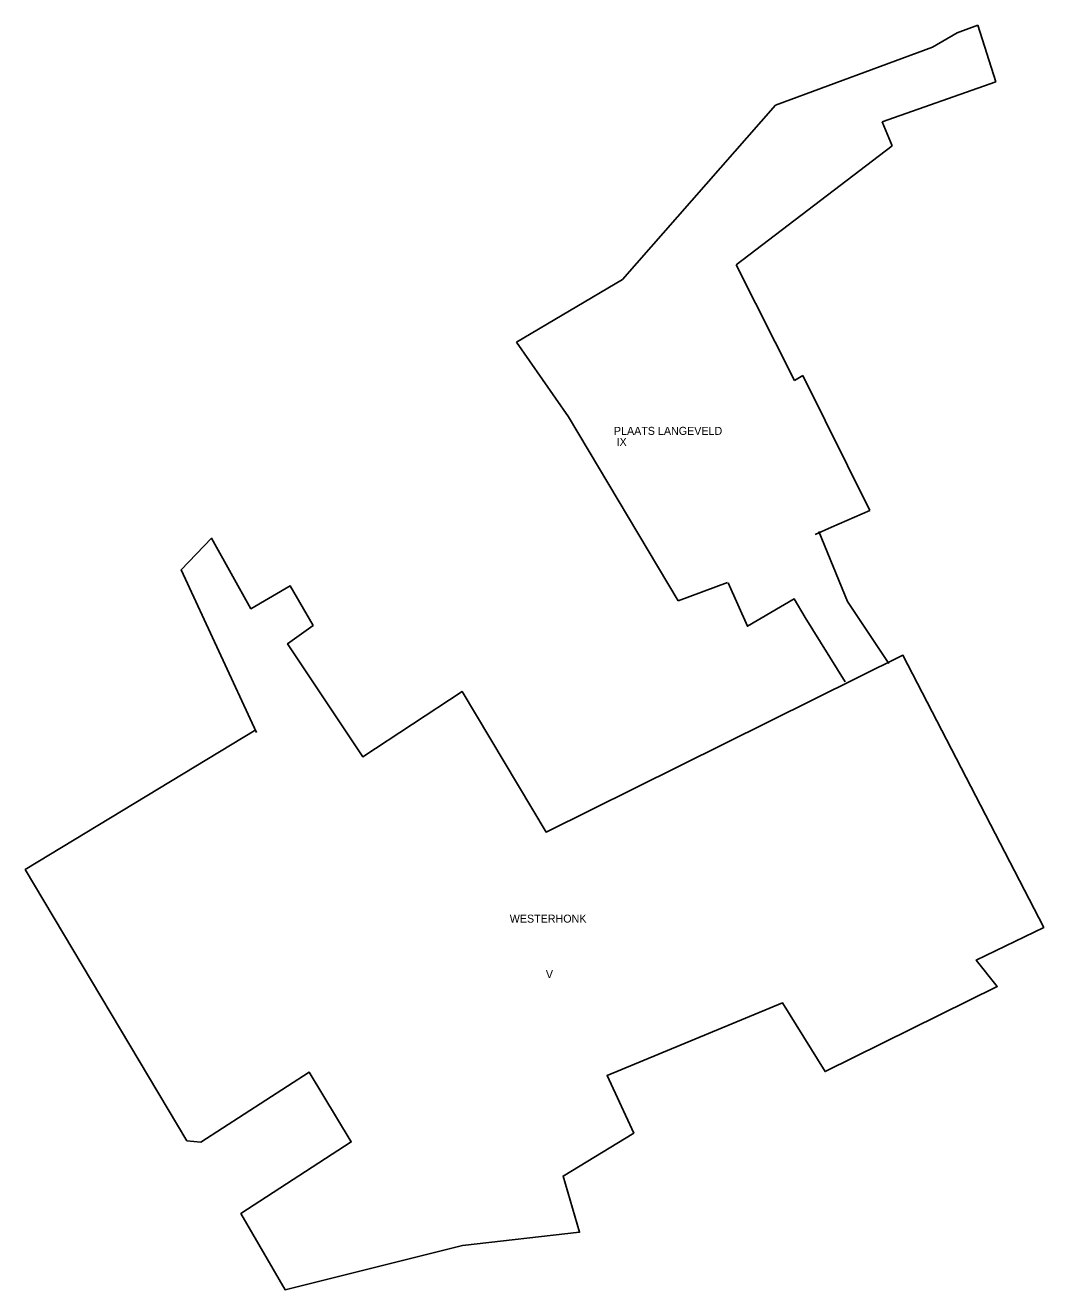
# Model space of a CAD drawing. Extents: x 69068 to 80855, y 440023 to 451362.
# Drawn here: x 72737 to 73882, y 449940 to 451362 of the extents above; entities that cross this region are included whole.
import ezdxf

# ---------------------------------------------------------------- set-up
doc = ezdxf.new("R2010")
doc.units = 0
for name, color, linetype in [('Bemalingsgebiedsgrens', 7, 'Continuous'), ('Bemalingsgebiedsnummer', 7, 'Continuous'), ('RIO_Leidingen', 7, 'Continuous')]:
    doc.layers.add(name, color=color, linetype=linetype)

msp = doc.modelspace()

# ---------------------------------------------------------------- linework, layer by layer
at = {"layer": 'Bemalingsgebiedsgrens'}
for p, q in [((73784.5, 451353), (73807.9, 451361.6)), ((73784.5, 451353), (73807.9, 451361.6)), ((73784.5, 451353), (73807.9, 451361.6)), ((73784.5, 451353), (73807.9, 451361.6)), ((73807.9, 451361.6), (73828, 451298.1)), ((73807.9, 451361.6), (73828, 451298.1)), ((73807.9, 451361.6), (73828, 451298.1)), ((73807.9, 451361.6), (73828, 451298.1)), ((73756.8, 451337), (73784.5, 451353)), ((73756.8, 451337), (73784.5, 451353)), ((73756.8, 451337), (73784.5, 451353)), ((73756.8, 451337), (73784.5, 451353)), ((73580.2, 451271.6), (73756.8, 451337)), ((73580.2, 451271.6), (73756.8, 451337)), ((73580.2, 451271.6), (73756.8, 451337)), ((73580.2, 451271.6), (73756.8, 451337)), ((73828, 451298.1), (73700.1, 451252.9)), ((73828, 451298.1), (73700.1, 451252.9)), ((73828, 451298.1), (73700.1, 451252.9)), ((73828, 451298.1), (73700.1, 451252.9)), ((73408.2, 451075.7), (73580.2, 451271.6)), ((73408.2, 451075.7), (73580.2, 451271.6)), ((73408.2, 451075.7), (73580.2, 451271.6)), ((73408.2, 451075.7), (73580.2, 451271.6)), ((73700.1, 451252.9), (73711.4, 451226.1)), ((73700.1, 451252.9), (73711.4, 451226.1)), ((73700.1, 451252.9), (73711.4, 451226.1)), ((73700.1, 451252.9), (73711.4, 451226.1)), ((73711.4, 451226.1), (73536, 451092.2)), ((73711.4, 451226.1), (73536, 451092.2)), ((73711.4, 451226.1), (73536, 451092.2)), ((73711.4, 451226.1), (73536, 451092.2)), ((73536, 451092.2), (73601.5, 450962.3)), ((73536, 451092.2), (73601.5, 450962.3)), ((73536, 451092.2), (73601.5, 450962.3)), ((73536, 451092.2), (73601.5, 450962.3)), ((73289.1, 451005.5), (73408.2, 451075.7)), ((73289.1, 451005.5), (73408.2, 451075.7)), ((73289.1, 451005.5), (73408.2, 451075.7)), ((73289.1, 451005.5), (73408.2, 451075.7)), ((73347.5, 450921.5), (73289.1, 451005.5)), ((73347.5, 450921.5), (73289.1, 451005.5)), ((73347.5, 450921.5), (73289.1, 451005.5)), ((73347.5, 450921.5), (73289.1, 451005.5)), ((73601.5, 450962.3), (73611.2, 450967.7)), ((73601.5, 450962.3), (73611.2, 450967.7)), ((73601.5, 450962.3), (73611.2, 450967.7)), ((73601.5, 450962.3), (73611.2, 450967.7)), ((73611.2, 450967.7), (73686.3, 450816.2)), ((73611.2, 450967.7), (73686.3, 450816.2)), ((73611.2, 450967.7), (73686.3, 450816.2)), ((73611.2, 450967.7), (73686.3, 450816.2)), ((73470.9, 450714.4), (73347.5, 450921.5)), ((73470.9, 450714.4), (73347.5, 450921.5)), ((73470.9, 450714.4), (73347.5, 450921.5)), ((73470.9, 450714.4), (73347.5, 450921.5)), ((73686.3, 450816.2), (73643.1, 450797.4)), ((73686.3, 450816.2), (73643.1, 450797.4)), ((73686.3, 450816.2), (73643.1, 450797.4)), ((73686.3, 450816.2), (73643.1, 450797.4)), ((73643.1, 450797.4), (73625, 450789.2)), ((73643.1, 450797.4), (73625, 450789.2)), ((73643.1, 450797.4), (73625, 450789.2)), ((73643.1, 450797.4), (73625, 450789.2)), ((73526.4, 450735.1), (73470.9, 450714.4)), ((73526.4, 450735.1), (73470.9, 450714.4)), ((73526.4, 450735.1), (73470.9, 450714.4)), ((73526.4, 450735.1), (73470.9, 450714.4))]:
    msp.add_line(p, q, dxfattribs=at)
for points in [[(73707.7, 450643.9), (73661.3, 450713.8), (73629, 450792.6)], [(73707.7, 450643.9), (73661.3, 450713.8), (73629, 450792.6)], [(73707.7, 450643.9), (73661.3, 450713.8), (73629, 450792.6)], [(73707.7, 450643.9), (73661.3, 450713.8), (73629, 450792.6)], [(72996.2, 450569.6), (72737.1, 450412.4), (72918.7, 450107.5), (72934.4, 450106), (73056.3, 450184.4), (73103.4, 450106.2), (72979.4, 450025.6), (73029, 449940), (73228.6, 449989.6), (73360.1, 450004.5), (73341.5, 450067.8), (73420.9, 450116.1), (73391.1, 450180.7), (73588.3, 450262.5), (73636.1, 450185.3), (73829.6, 450280.9), (73806, 450310.6), (73881.8, 450347.4), (73723.6, 450653.4), (73322.4, 450454.5), (73228.1, 450612.7), (73116.3, 450539.2), (73116.3, 450539.2), (73031.9, 450666.2), (73060.6, 450686.9), (73034.9, 450731.2), (72990.6, 450705.6), (72946.4, 450784.9), (72912.1, 450749.2), (72997, 450566.6)], [(72996.2, 450569.6), (72737.1, 450412.4), (72918.7, 450107.5), (72934.4, 450106), (73056.3, 450184.4), (73103.4, 450106.2), (72979.4, 450025.6), (73029, 449940), (73228.6, 449989.6), (73360.1, 450004.5), (73341.5, 450067.8), (73420.9, 450116.1), (73391.1, 450180.7), (73588.3, 450262.5), (73636.1, 450185.3), (73829.6, 450280.9), (73806, 450310.6), (73881.8, 450347.4), (73723.6, 450653.4), (73322.4, 450454.5), (73228.1, 450612.7), (73116.3, 450539.2), (73116.3, 450539.2), (73031.9, 450666.2), (73060.6, 450686.9), (73034.9, 450731.2), (72990.6, 450705.6), (72946.4, 450784.9), (72912.1, 450749.2), (72997, 450566.6)], [(72996.2, 450569.6), (72737.1, 450412.4), (72918.7, 450107.5), (72934.4, 450106), (73056.3, 450184.4), (73103.4, 450106.2), (72979.4, 450025.6), (73029, 449940), (73228.6, 449989.6), (73360.1, 450004.5), (73341.5, 450067.8), (73420.9, 450116.1), (73391.1, 450180.7), (73588.3, 450262.5), (73636.1, 450185.3), (73829.6, 450280.9), (73806, 450310.6), (73881.8, 450347.4), (73723.6, 450653.4), (73322.4, 450454.5), (73228.1, 450612.7), (73116.3, 450539.2), (73116.3, 450539.2), (73031.9, 450666.2), (73060.6, 450686.9), (73034.9, 450731.2), (72990.6, 450705.6), (72946.4, 450784.9), (72912.1, 450749.2), (72997, 450566.6)], [(72996.2, 450569.6), (72737.1, 450412.4), (72918.7, 450107.5), (72934.4, 450106), (73056.3, 450184.4), (73103.4, 450106.2), (72979.4, 450025.6), (73029, 449940), (73228.6, 449989.6), (73360.1, 450004.5), (73341.5, 450067.8), (73420.9, 450116.1), (73391.1, 450180.7), (73588.3, 450262.5), (73636.1, 450185.3), (73829.6, 450280.9), (73806, 450310.6), (73881.8, 450347.4), (73723.6, 450653.4), (73322.4, 450454.5), (73228.1, 450612.7), (73116.3, 450539.2), (73116.3, 450539.2), (73031.9, 450666.2), (73060.6, 450686.9), (73034.9, 450731.2), (72990.6, 450705.6), (72946.4, 450784.9), (72912.1, 450749.2), (72997, 450566.6)], [(73527.1, 450734.8), (73548.8, 450686), (73601.3, 450716.9), (73613.7, 450695.6), (73658.6, 450623.3)], [(73527.1, 450734.8), (73548.8, 450686), (73601.3, 450716.9), (73613.7, 450695.6), (73658.6, 450623.3)], [(73527.1, 450734.8), (73548.8, 450686), (73601.3, 450716.9), (73613.7, 450695.6), (73658.6, 450623.3)], [(73527.1, 450734.8), (73548.8, 450686), (73601.3, 450716.9), (73613.7, 450695.6), (73658.6, 450623.3)]]:
    msp.add_lwpolyline(points, dxfattribs=at)

# ---------------------------------------------------------------- texts
at = {"layer": 'Bemalingsgebiedsnummer'}
for s, p in [('IX', (73401.7, 450888.7)), ('IX', (73401.7, 450888.7)), ('IX', (73401.7, 450888.7)), ('IX', (73401.7, 450888.7)), ('V', (73322.2, 450290.3)), ('V', (73322.2, 450290.3)), ('V', (73322.2, 450290.3)), ('V', (73322.2, 450290.3))]:
    msp.add_text(s, height=9, dxfattribs=at).set_placement(p)
at = {"layer": 'RIO_Leidingen'}
for s, p in [('PLAATS LANGEVELD', (73398.7, 450901.1)), ('PLAATS LANGEVELD', (73398.7, 450901.1)), ('PLAATS LANGEVELD', (73398.7, 450901.1)), ('PLAATS LANGEVELD', (73398.7, 450901.1)), ('WESTERHONK', (73281.6, 450352.7)), ('WESTERHONK', (73281.6, 450352.7)), ('WESTERHONK', (73281.6, 450352.7)), ('WESTERHONK', (73281.6, 450352.7))]:
    msp.add_text(s, height=9, dxfattribs=at).set_placement(p)

doc.saveas('drawing.dxf')
